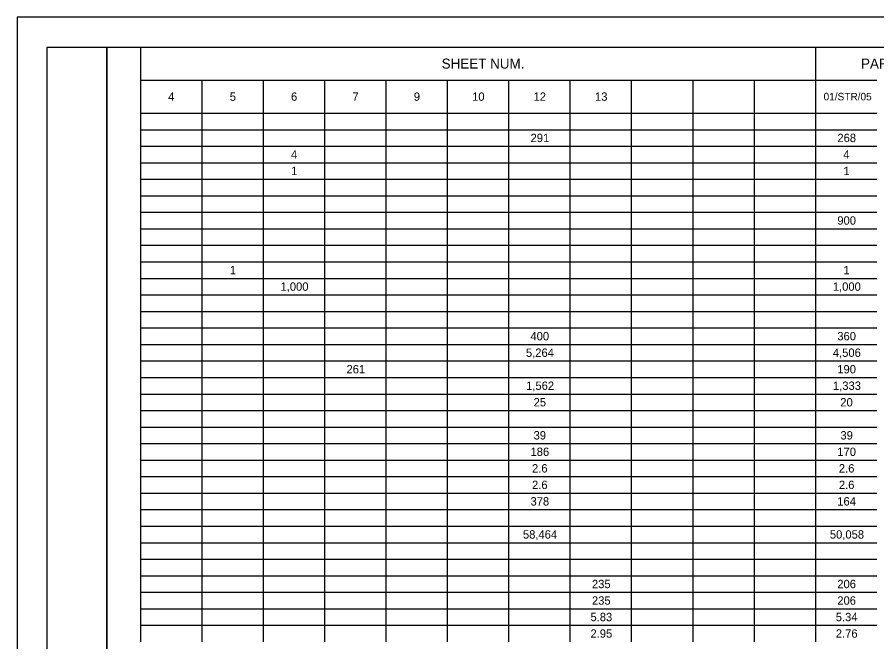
# Model space of a CAD drawing. Extents: x 0 to 34, y 0 to 22.
# Drawn here: x 0 to 14.4, y 11.54 to 22 of the extents above; entities that cross this region are included whole.
import ezdxf

# ---------------------------------------------------------------- set-up
doc = ezdxf.new("R2010")
doc.units = 0
for name, color, linetype in [('Default', 7, 'Continuous'), ('SH_Border', 7, 'Continuous'), ('SH_Cut_Line', 7, 'Continuous')]:
    doc.layers.add(name, color=color, linetype=linetype)

msp = doc.modelspace()

# ---------------------------------------------------------------- linework, layer by layer
at = {"layer": 'Default'}
for p, q in [((2.063, 21.5), (7.202, 21.5)), ((2.063, 21.5), (2.063, 21.223)), ((7.202, 21.5), (8.23, 21.5)), ((8.23, 21.5), (13.368, 21.5)), ((13.368, 21.5), (14.396, 21.5)), ((13.368, 21.5), (13.368, 21.223)), ((2.063, 21.223), (2.063, 20.947)), ((13.368, 21.223), (13.368, 20.947)), ((2.063, 20.947), (7.202, 20.947)), ((2.063, 20.947), (2.063, 20.67)), ((3.091, 20.947), (3.091, 20.67)), ((4.119, 20.947), (4.119, 20.67)), ((5.146, 20.947), (5.146, 20.67)), ((6.174, 20.947), (6.174, 20.67)), ((7.202, 20.947), (8.23, 20.947)), ((7.202, 20.947), (7.202, 20.67)), ((8.23, 20.947), (13.368, 20.947)), ((8.23, 20.947), (8.23, 20.67)), ((9.257, 20.947), (9.257, 20.67)), ((10.285, 20.947), (10.285, 20.67)), ((11.313, 20.947), (11.313, 20.67)), ((12.341, 20.947), (12.341, 20.67)), ((13.368, 20.947), (14.396, 20.947)), ((13.368, 20.947), (13.368, 20.67)), ((2.063, 20.67), (2.063, 20.393)), ((3.091, 20.67), (3.091, 20.393)), ((4.119, 20.67), (4.119, 20.393)), ((5.146, 20.67), (5.146, 20.393)), ((6.174, 20.67), (6.174, 20.393)), ((7.202, 20.67), (7.202, 20.393)), ((8.23, 20.67), (8.23, 20.393)), ((9.257, 20.67), (9.257, 20.393)), ((10.285, 20.67), (10.285, 20.393)), ((11.313, 20.67), (11.313, 20.393)), ((12.341, 20.67), (12.341, 20.393)), ((13.368, 20.67), (13.368, 20.393)), ((2.063, 20.393), (7.202, 20.393)), ((2.063, 20.393), (2.063, 20.116)), ((3.091, 20.393), (3.091, 20.116)), ((4.119, 20.393), (4.119, 20.116)), ((5.146, 20.393), (5.146, 20.116)), ((6.174, 20.393), (6.174, 20.116)), ((7.202, 20.393), (8.23, 20.393)), ((7.202, 20.393), (7.202, 20.116)), ((8.23, 20.393), (13.368, 20.393)), ((8.23, 20.393), (8.23, 20.116)), ((9.257, 20.393), (9.257, 20.116)), ((10.285, 20.393), (10.285, 20.116)), ((11.313, 20.393), (11.313, 20.116)), ((12.341, 20.393), (12.341, 20.116)), ((13.368, 20.393), (14.396, 20.393)), ((13.368, 20.393), (13.368, 20.116)), ((2.063, 20.116), (7.202, 20.116)), ((2.063, 20.116), (2.063, 18.733)), ((3.091, 20.116), (3.091, 18.733)), ((4.119, 20.116), (4.119, 18.733)), ((5.146, 20.116), (5.146, 18.733)), ((6.174, 20.116), (6.174, 18.733)), ((7.202, 20.116), (8.23, 20.116)), ((7.202, 20.116), (7.202, 18.733)), ((8.23, 20.116), (13.368, 20.116)), ((8.23, 20.116), (8.23, 18.733)), ((9.257, 20.116), (9.257, 18.733)), ((10.285, 20.116), (10.285, 18.733)), ((11.313, 20.116), (11.313, 18.733)), ((12.341, 20.116), (12.341, 18.733)), ((13.368, 20.116), (14.396, 20.116)), ((13.368, 20.116), (13.368, 18.733)), ((2.063, 19.84), (7.202, 19.84)), ((7.202, 19.84), (8.23, 19.84)), ((8.23, 19.84), (13.368, 19.84)), ((13.368, 19.84), (14.396, 19.84)), ((2.063, 19.563), (7.202, 19.563)), ((7.202, 19.563), (8.23, 19.563)), ((8.23, 19.563), (13.368, 19.563)), ((13.368, 19.563), (14.396, 19.563)), ((2.063, 19.286), (7.202, 19.286)), ((7.202, 19.286), (8.23, 19.286)), ((8.23, 19.286), (13.368, 19.286)), ((13.368, 19.286), (14.396, 19.286)), ((2.063, 19.01), (7.202, 19.01)), ((7.202, 19.01), (8.23, 19.01)), ((8.23, 19.01), (13.368, 19.01)), ((13.368, 19.01), (14.396, 19.01)), ((2.063, 18.733), (7.202, 18.733)), ((2.063, 18.733), (2.063, 18.18)), ((3.091, 18.733), (3.091, 18.18)), ((4.119, 18.733), (4.119, 18.18)), ((5.146, 18.733), (5.146, 18.18)), ((6.174, 18.733), (6.174, 18.18)), ((7.202, 18.733), (8.23, 18.733)), ((7.202, 18.733), (7.202, 18.18)), ((8.23, 18.733), (13.368, 18.733)), ((8.23, 18.733), (8.23, 18.18)), ((9.257, 18.733), (9.257, 18.18)), ((10.285, 18.733), (10.285, 18.18)), ((11.313, 18.733), (11.313, 18.18)), ((12.341, 18.733), (12.341, 18.18)), ((13.368, 18.733), (14.396, 18.733)), ((13.368, 18.733), (13.368, 18.18)), ((2.063, 18.456), (7.202, 18.456)), ((7.202, 18.456), (8.23, 18.456)), ((8.23, 18.456), (13.368, 18.456)), ((13.368, 18.456), (14.396, 18.456)), ((2.063, 18.18), (7.202, 18.18)), ((2.063, 18.18), (2.063, 17.903)), ((3.091, 18.18), (3.091, 17.903)), ((4.119, 18.18), (4.119, 17.903)), ((5.146, 18.18), (5.146, 17.903)), ((6.174, 18.18), (6.174, 17.903)), ((7.202, 18.18), (8.23, 18.18)), ((7.202, 18.18), (7.202, 17.903)), ((8.23, 18.18), (13.368, 18.18)), ((8.23, 18.18), (8.23, 17.903)), ((9.257, 18.18), (9.257, 17.903)), ((10.285, 18.18), (10.285, 17.903)), ((11.313, 18.18), (11.313, 17.903)), ((12.341, 18.18), (12.341, 17.903)), ((13.368, 18.18), (14.396, 18.18)), ((13.368, 18.18), (13.368, 17.903)), ((2.063, 17.903), (7.202, 17.903)), ((2.063, 17.903), (2.063, 17.626)), ((3.091, 17.903), (3.091, 17.626)), ((4.119, 17.903), (4.119, 17.626)), ((5.146, 17.903), (5.146, 17.626)), ((6.174, 17.903), (6.174, 17.626)), ((7.202, 17.903), (8.23, 17.903)), ((7.202, 17.903), (7.202, 17.626)), ((8.23, 17.903), (13.368, 17.903)), ((8.23, 17.903), (8.23, 17.626)), ((9.257, 17.903), (9.257, 17.626)), ((10.285, 17.903), (10.285, 17.626)), ((11.313, 17.903), (11.313, 17.626)), ((12.341, 17.903), (12.341, 17.626)), ((13.368, 17.903), (14.396, 17.903)), ((13.368, 17.903), (13.368, 17.626)), ((2.063, 17.626), (7.202, 17.626)), ((2.063, 17.626), (2.063, 17.349)), ((3.091, 17.626), (3.091, 17.349)), ((4.119, 17.626), (4.119, 17.349)), ((5.146, 17.626), (5.146, 17.349)), ((6.174, 17.626), (6.174, 17.349)), ((7.202, 17.626), (8.23, 17.626)), ((7.202, 17.626), (7.202, 17.349)), ((8.23, 17.626), (13.368, 17.626)), ((8.23, 17.626), (8.23, 17.349)), ((9.257, 17.626), (9.257, 17.349)), ((10.285, 17.626), (10.285, 17.349)), ((11.313, 17.626), (11.313, 17.349)), ((12.341, 17.626), (12.341, 17.349)), ((13.368, 17.626), (14.396, 17.626)), ((13.368, 17.626), (13.368, 17.349)), ((2.063, 17.349), (7.202, 17.349)), ((2.063, 17.349), (2.063, 17.073)), ((3.091, 17.349), (3.091, 17.073)), ((4.119, 17.349), (4.119, 17.073)), ((5.146, 17.349), (5.146, 17.073)), ((6.174, 17.349), (6.174, 17.073)), ((7.202, 17.349), (8.23, 17.349)), ((7.202, 17.349), (7.202, 17.073)), ((8.23, 17.349), (13.368, 17.349)), ((8.23, 17.349), (8.23, 17.073)), ((9.257, 17.349), (9.257, 17.073)), ((10.285, 17.349), (10.285, 17.073)), ((11.313, 17.349), (11.313, 17.073)), ((12.341, 17.349), (12.341, 17.073)), ((13.368, 17.349), (14.396, 17.349)), ((13.368, 17.349), (13.368, 17.073)), ((2.063, 17.073), (7.202, 17.073)), ((2.063, 17.073), (2.063, 16.796)), ((3.091, 17.073), (3.091, 16.796)), ((4.119, 17.073), (4.119, 16.796)), ((5.146, 17.073), (5.146, 16.796)), ((6.174, 17.073), (6.174, 16.796)), ((7.202, 17.073), (8.23, 17.073)), ((7.202, 17.073), (7.202, 16.796)), ((8.23, 17.073), (13.368, 17.073)), ((8.23, 17.073), (8.23, 16.796)), ((9.257, 17.073), (9.257, 16.796)), ((10.285, 17.073), (10.285, 16.796)), ((11.313, 17.073), (11.313, 16.796)), ((12.341, 17.073), (12.341, 16.796)), ((13.368, 17.073), (14.396, 17.073)), ((13.368, 17.073), (13.368, 16.796)), ((2.063, 16.796), (7.202, 16.796)), ((2.063, 16.796), (2.063, 16.243)), ((3.091, 16.796), (3.091, 16.243)), ((4.119, 16.796), (4.119, 16.243)), ((5.146, 16.796), (5.146, 16.243)), ((6.174, 16.796), (6.174, 16.243)), ((7.202, 16.796), (8.23, 16.796)), ((7.202, 16.796), (7.202, 16.243)), ((8.23, 16.796), (13.368, 16.796)), ((8.23, 16.796), (8.23, 16.243)), ((9.257, 16.796), (9.257, 16.243)), ((10.285, 16.796), (10.285, 16.243)), ((11.313, 16.796), (11.313, 16.243)), ((12.341, 16.796), (12.341, 16.243)), ((13.368, 16.796), (14.396, 16.796)), ((13.368, 16.796), (13.368, 16.243)), ((2.063, 16.519), (7.202, 16.519)), ((7.202, 16.519), (8.23, 16.519)), ((8.23, 16.519), (13.368, 16.519)), ((13.368, 16.519), (14.396, 16.519)), ((2.063, 16.243), (7.202, 16.243)), ((2.063, 16.243), (2.063, 15.966)), ((3.091, 16.243), (3.091, 15.966)), ((4.119, 16.243), (4.119, 15.966)), ((5.146, 16.243), (5.146, 15.966)), ((6.174, 16.243), (6.174, 15.966)), ((7.202, 16.243), (8.23, 16.243)), ((7.202, 16.243), (7.202, 15.966)), ((8.23, 16.243), (13.368, 16.243)), ((8.23, 16.243), (8.23, 15.966)), ((9.257, 16.243), (9.257, 15.966)), ((10.285, 16.243), (10.285, 15.966)), ((11.313, 16.243), (11.313, 15.966)), ((12.341, 16.243), (12.341, 15.966)), ((13.368, 16.243), (14.396, 16.243)), ((13.368, 16.243), (13.368, 15.966)), ((2.063, 15.966), (7.202, 15.966)), ((2.063, 15.966), (2.063, 15.689)), ((3.091, 15.966), (3.091, 15.689)), ((4.119, 15.966), (4.119, 15.689)), ((5.146, 15.966), (5.146, 15.689)), ((6.174, 15.966), (6.174, 15.689)), ((7.202, 15.966), (8.23, 15.966)), ((7.202, 15.966), (7.202, 15.689)), ((8.23, 15.966), (13.368, 15.966)), ((8.23, 15.966), (8.23, 15.689)), ((9.257, 15.966), (9.257, 15.689)), ((10.285, 15.966), (10.285, 15.689)), ((11.313, 15.966), (11.313, 15.689)), ((12.341, 15.966), (12.341, 15.689)), ((13.368, 15.966), (14.396, 15.966)), ((13.368, 15.966), (13.368, 15.689)), ((2.063, 15.689), (7.202, 15.689)), ((2.063, 15.689), (2.063, 15.412)), ((3.091, 15.689), (3.091, 15.412)), ((4.119, 15.689), (4.119, 15.412)), ((5.146, 15.689), (5.146, 15.412)), ((6.174, 15.689), (6.174, 15.412)), ((7.202, 15.689), (8.23, 15.689)), ((7.202, 15.689), (7.202, 15.412)), ((8.23, 15.689), (13.368, 15.689)), ((8.23, 15.689), (8.23, 15.412)), ((9.257, 15.689), (9.257, 15.412)), ((10.285, 15.689), (10.285, 15.412)), ((11.313, 15.689), (11.313, 15.412)), ((12.341, 15.689), (12.341, 15.412)), ((13.368, 15.689), (14.396, 15.689)), ((13.368, 15.689), (13.368, 15.412)), ((2.063, 15.412), (7.202, 15.412)), ((2.063, 15.412), (2.063, 14.859)), ((3.091, 15.412), (3.091, 14.859)), ((4.119, 15.412), (4.119, 14.859)), ((5.146, 15.412), (5.146, 14.859)), ((6.174, 15.412), (6.174, 14.859)), ((7.202, 15.412), (8.23, 15.412)), ((7.202, 15.412), (7.202, 14.859)), ((8.23, 15.412), (13.368, 15.412)), ((8.23, 15.412), (8.23, 14.859)), ((9.257, 15.412), (9.257, 14.859)), ((10.285, 15.412), (10.285, 14.859)), ((11.313, 15.412), (11.313, 14.859)), ((12.341, 15.412), (12.341, 14.859)), ((13.368, 15.412), (14.396, 15.412)), ((13.368, 15.412), (13.368, 14.859)), ((2.063, 15.136), (7.202, 15.136)), ((7.202, 15.136), (8.23, 15.136)), ((8.23, 15.136), (13.368, 15.136)), ((13.368, 15.136), (14.396, 15.136)), ((2.063, 14.859), (7.202, 14.859)), ((2.063, 14.859), (2.063, 14.582)), ((3.091, 14.859), (3.091, 14.582)), ((4.119, 14.859), (4.119, 14.582)), ((5.146, 14.859), (5.146, 14.582)), ((6.174, 14.859), (6.174, 14.582)), ((7.202, 14.859), (8.23, 14.859)), ((7.202, 14.859), (7.202, 14.582)), ((8.23, 14.859), (13.368, 14.859)), ((8.23, 14.859), (8.23, 14.582)), ((9.257, 14.859), (9.257, 14.582)), ((10.285, 14.859), (10.285, 14.582)), ((11.313, 14.859), (11.313, 14.582)), ((12.341, 14.859), (12.341, 14.582)), ((13.368, 14.859), (14.396, 14.859)), ((13.368, 14.859), (13.368, 14.582)), ((2.063, 14.582), (7.202, 14.582)), ((2.063, 14.582), (2.063, 14.306)), ((3.091, 14.582), (3.091, 14.306)), ((4.119, 14.582), (4.119, 14.306)), ((5.146, 14.582), (5.146, 14.306)), ((6.174, 14.582), (6.174, 14.306)), ((7.202, 14.582), (8.23, 14.582)), ((7.202, 14.582), (7.202, 14.306)), ((8.23, 14.582), (13.368, 14.582)), ((8.23, 14.582), (8.23, 14.306)), ((9.257, 14.582), (9.257, 14.306)), ((10.285, 14.582), (10.285, 14.306)), ((11.313, 14.582), (11.313, 14.306)), ((12.341, 14.582), (12.341, 14.306)), ((13.368, 14.582), (14.396, 14.582)), ((13.368, 14.582), (13.368, 14.306)), ((2.063, 14.306), (7.202, 14.306)), ((2.063, 14.306), (2.063, 14.029)), ((3.091, 14.306), (3.091, 14.029)), ((4.119, 14.306), (4.119, 14.029)), ((5.146, 14.306), (5.146, 14.029)), ((6.174, 14.306), (6.174, 14.029)), ((7.202, 14.306), (8.23, 14.306)), ((7.202, 14.306), (7.202, 14.029)), ((8.23, 14.306), (13.368, 14.306)), ((8.23, 14.306), (8.23, 14.029)), ((9.257, 14.306), (9.257, 14.029)), ((10.285, 14.306), (10.285, 14.029)), ((11.313, 14.306), (11.313, 14.029)), ((12.341, 14.306), (12.341, 14.029)), ((13.368, 14.306), (14.396, 14.306)), ((13.368, 14.306), (13.368, 14.029)), ((2.063, 14.029), (7.202, 14.029)), ((2.063, 14.029), (2.063, 11.815)), ((3.091, 14.029), (3.091, 11.815)), ((4.119, 14.029), (4.119, 11.815)), ((5.146, 14.029), (5.146, 11.815)), ((6.174, 14.029), (6.174, 11.815)), ((7.202, 14.029), (8.23, 14.029)), ((7.202, 14.029), (7.202, 11.815)), ((8.23, 14.029), (13.368, 14.029)), ((8.23, 14.029), (8.23, 11.815)), ((9.257, 14.029), (9.257, 11.815)), ((10.285, 14.029), (10.285, 11.815)), ((11.313, 14.029), (11.313, 11.815)), ((12.341, 14.029), (12.341, 11.815)), ((13.368, 14.029), (14.396, 14.029)), ((13.368, 14.029), (13.368, 11.815)), ((2.063, 13.752), (7.202, 13.752)), ((7.202, 13.752), (8.23, 13.752)), ((8.23, 13.752), (13.368, 13.752)), ((13.368, 13.752), (14.396, 13.752)), ((2.063, 13.476), (7.202, 13.476)), ((7.202, 13.476), (8.23, 13.476)), ((8.23, 13.476), (13.368, 13.476)), ((13.368, 13.476), (14.396, 13.476)), ((2.063, 13.199), (7.202, 13.199)), ((7.202, 13.199), (8.23, 13.199)), ((8.23, 13.199), (13.368, 13.199)), ((13.368, 13.199), (14.396, 13.199)), ((2.063, 12.922), (7.202, 12.922)), ((7.202, 12.922), (8.23, 12.922)), ((8.23, 12.922), (13.368, 12.922)), ((13.368, 12.922), (14.396, 12.922)), ((2.063, 12.645), (7.202, 12.645)), ((7.202, 12.645), (8.23, 12.645)), ((8.23, 12.645), (13.368, 12.645)), ((13.368, 12.645), (14.396, 12.645)), ((2.063, 12.369), (7.202, 12.369)), ((7.202, 12.369), (8.23, 12.369)), ((8.23, 12.369), (13.368, 12.369)), ((13.368, 12.369), (14.396, 12.369)), ((2.063, 12.092), (7.202, 12.092)), ((7.202, 12.092), (8.23, 12.092)), ((8.23, 12.092), (13.368, 12.092)), ((13.368, 12.092), (14.396, 12.092)), ((2.063, 11.815), (7.202, 11.815)), ((2.063, 11.815), (2.063, 11.539)), ((3.091, 11.815), (3.091, 11.539)), ((4.119, 11.815), (4.119, 11.539)), ((5.146, 11.815), (5.146, 11.539)), ((6.174, 11.815), (6.174, 11.539)), ((7.202, 11.815), (8.23, 11.815)), ((7.202, 11.815), (7.202, 11.539)), ((8.23, 11.815), (13.368, 11.815)), ((8.23, 11.815), (8.23, 11.539)), ((9.257, 11.815), (9.257, 11.539)), ((10.285, 11.815), (10.285, 11.539)), ((11.313, 11.815), (11.313, 11.539)), ((12.341, 11.815), (12.341, 11.539)), ((13.368, 11.815), (14.396, 11.815)), ((13.368, 11.815), (13.368, 11.539))]:
    msp.add_line(p, q, dxfattribs=at)
at = {"layer": 'SH_Border'}
for points in [[(0.5, 21.5), (1.5, 21.5), (1.5, 0.5), (0.5, 0.5)], [(1.5, 21.5), (33.5, 21.5), (33.5, 0.5), (1.5, 0.5)]]:
    msp.add_lwpolyline(points, close=True, dxfattribs=at)
at = {"layer": 'SH_Cut_Line'}
msp.add_lwpolyline([(0, 0), (34, 0), (34, 22), (0, 22)], close=True, dxfattribs=at)

# ---------------------------------------------------------------- texts
at = {"layer": 'Default'}
for s, height, p in [('SHEET NUM.', 0.168, (7.109, 21.139)), ('PART.', 0.168, (14.132, 21.139)), ('4', 0.14, (2.529, 20.6)), ('5', 0.14, (3.56, 20.6)), ('6', 0.14, (4.586, 20.6)), ('7', 0.14, (5.614, 20.6)), ('9', 0.14, (6.643, 20.6)), ('10', 0.14, (7.619, 20.6)), ('12', 0.14, (8.648, 20.6)), ('13', 0.14, (9.677, 20.6)), ('01/STR/05', 0.126, (13.505, 20.607)), ('291', 0.14, (8.598, 19.908)), ('268', 0.14, (13.736, 19.908)), ('4', 0.14, (4.585, 19.631)), ('4', 0.14, (13.835, 19.631)), ('1', 0.14, (4.588, 19.355)), ('1', 0.14, (13.837, 19.355)), ('900', 0.14, (13.735, 18.525)), ('1', 0.14, (3.56, 17.694)), ('1', 0.14, (13.837, 17.694)), ('1,000', 0.14, (4.41, 17.418)), ('1,000', 0.14, (13.66, 17.418)), ('400', 0.14, (8.596, 16.588)), ('360', 0.14, (13.735, 16.588)), ('5,264', 0.14, (8.52, 16.311)), ('4,506', 0.14, (13.66, 16.311)), ('261', 0.14, (5.515, 16.034)), ('190', 0.14, (13.735, 16.034)), ('1,562', 0.14, (8.523, 15.758)), ('1,333', 0.14, (13.662, 15.758)), ('25', 0.14, (8.649, 15.481)), ('20', 0.14, (13.785, 15.481)), ('39', 0.14, (8.648, 14.927)), ('39', 0.14, (13.787, 14.927)), ('186', 0.14, (8.597, 14.651)), ('170', 0.14, (13.735, 14.651)), ('2.6', 0.14, (8.622, 14.374)), ('2.6', 0.14, (13.761, 14.374)), ('2.6', 0.14, (8.622, 14.097)), ('2.6', 0.14, (13.761, 14.097)), ('378', 0.14, (8.597, 13.821)), ('164', 0.14, (13.734, 13.821)), ('58,464', 0.14, (8.47, 13.267)), ('50,058', 0.14, (13.61, 13.267)), ('235', 0.14, (9.626, 12.437)), ('206', 0.14, (13.735, 12.437)), ('235', 0.14, (9.626, 12.16)), ('206', 0.14, (13.735, 12.16)), ('5.83', 0.14, (9.601, 11.884)), ('5.34', 0.14, (13.709, 11.884)), ('2.95', 0.14, (9.601, 11.607)), ('2.76', 0.14, (13.71, 11.607))]:
    msp.add_text(s, height=height, dxfattribs=at).set_placement(p)

doc.saveas('drawing.dxf')
